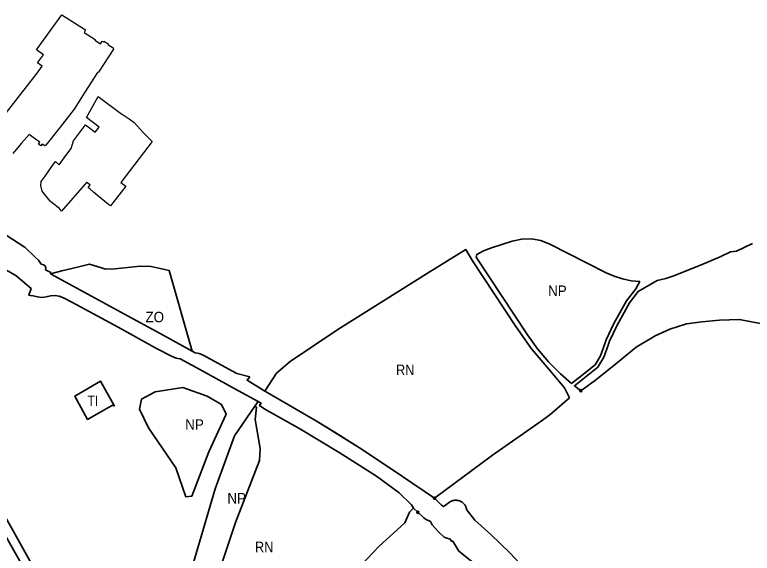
# Model space of a CAD drawing. Extents: x -650276 to -642489, y -1074311 to -1066658.
# Drawn here: x -646058 to -645218, y -1069228 to -1068615 of the extents above; entities that cross this region are included whole.
import ezdxf

# ---------------------------------------------------------------- set-up
doc = ezdxf.new("R2010")
doc.units = 0
doc.header["$LTSCALE"] = 4.8
doc.header["$PDMODE"] = 32
doc.header["$PDSIZE"] = 2.4
for name, color, linetype, lineweight in [('15', 7, 'Continuous', 35), ('24', 7, 'Continuous', 35), ('30', 7, 'Continuous', 35), ('42', 7, 'Continuous', 35), ('48', 7, 'Continuous', 35), ('61', 7, 'Continuous', 25), ('7', 7, 'Continuous', 35)]:
    doc.layers.add(name, color=color, linetype=linetype, lineweight=lineweight)
doc.layers.add('62', color=7, linetype='Continuous')

msp = doc.modelspace()

# ---------------------------------------------------------------- linework, layer by layer
at = {"layer": '15'}
msp.add_lwpolyline([(-646037.99, -1069242.88), (-646107, -1069119.41), (-646150.87, -1069037.64), (-646152.26, -1069038.76), (-646161.484, -1069046.228), (-646153.307, -1069059.947), (-646025.14, -1069285.394)], dxfattribs=at)
at = {"layer": '24'}
for points in [[(-645579.94, -1069165.52), (-645616.63, -1069140.8), (-645662.44, -1069109.89), (-645713.61, -1069078.06), (-645770.04, -1069045.34), (-645773.38, -1069043.46), (-645793.638, -1069031.021), (-645790.53, -1069027.19), (-645805.16, -1069023.52), (-645843.56, -1069002.41), (-645848.18, -1069000.48), (-645852.91, -1068999.62), (-645856.26, -1068997.79), (-645892.77, -1068977.86), (-645933.28, -1068955.74), (-645975.31, -1068932.8), (-646017.55, -1068909.75), (-646017.39, -1068908.42), (-646023.56, -1068905.05), (-646023.13, -1068903.12), (-646023.92, -1068900.73), (-646025.57, -1068899.39), (-646028.18, -1068898.89), (-646031.31, -1068894.32), (-646034.65, -1068891.12), (-646046.48, -1068879.92), (-646074.78, -1068861.51)], [(-646074.51, -1068901.9), (-646057.13, -1068911.62), (-646039.84, -1068926.67), (-646042.5, -1068933.91), (-646040.65, -1068934.59), (-646037.5, -1068934.7), (-646032.61, -1068936.1), (-646027.69, -1068936.6), (-646022.77, -1068936.12), (-646017.6, -1068934.89), (-646012.64, -1068934.34), (-646007.7, -1068935.18), (-646002.95, -1068936.95), (-645993.5, -1068942.1), (-645940.77, -1068970.74), (-645896.91, -1068994.75), (-645879.17, -1069004.02), (-645874.49, -1069005.73), (-645869.83, -1069006.45), (-645850.79, -1069016.84), (-645803.29, -1069042.92), (-645781.12, -1069055.29), (-645777.73, -1069057.2), (-645779.49, -1069059.92), (-645773.29, -1069063.99), (-645732.65, -1069086.82), (-645688.87, -1069113.44), (-645646.08, -1069140.37), (-645620.2, -1069159.26), (-645606.11, -1069172.98), (-645603.91, -1069176.86), (-645599, -1069181.48)], [(-645571.9, -1069173.43), (-645579.94, -1069165.52), (-645579.94, -1069165.52)], [(-645543.43, -1069178.39), (-645543.547, -1069177.727), (-645543.706, -1069177.053), (-645543.907, -1069176.37), (-645544.154, -1069175.682), (-645544.448, -1069174.993), (-645544.792, -1069174.308), (-645545.186, -1069173.63), (-645545.631, -1069172.966), (-645546.127, -1069172.32), (-645546.674, -1069171.699), (-645547.269, -1069171.107), (-645547.91, -1069170.551), (-645548.594, -1069170.034), (-645549.317, -1069169.563), (-645550.076, -1069169.141), (-645550.863, -1069168.772), (-645551.674, -1069168.459), (-645552.504, -1069168.203), (-645553.344, -1069168.007), (-645554.191, -1069167.87), (-645555.036, -1069167.793), (-645555.875, -1069167.772), (-645556.702, -1069167.808), (-645557.511, -1069167.896), (-645558.298, -1069168.035), (-645559.06, -1069168.219), (-645559.793, -1069168.445), (-645560.494, -1069168.709), (-645561.162, -1069169.007), (-645561.794, -1069169.334), (-645562.39, -1069169.686), (-645562.95, -1069170.06), (-645567.5, -1069173.46), (-645569.81, -1069175.03), (-645571.9, -1069173.43)], [(-645599, -1069181.48), (-645599, -1069181.48), (-645592.24, -1069187.73), (-645590.41, -1069189.45), (-645584.73, -1069191.88), (-645582.63, -1069195.88), (-645575.58, -1069203.57), (-645568.9, -1069209.87), (-645567.07, -1069210.45), (-645562.17, -1069212.02), (-645560.72, -1069214.25), (-645559.33, -1069214.54), (-645552.2, -1069225.59), (-645537.44, -1069237.41)], [(-645202.56, -1069568.23), (-645230.1, -1069525.98), (-645253.4, -1069493.06), (-645278.31, -1069461.33), (-645281.4, -1069458.4), (-645290.5, -1069449.03), (-645299.61, -1069437.97), (-645306.16, -1069425.55), (-645314.14, -1069412.54), (-645321.1, -1069405.21), (-645326.59, -1069396.64), (-645350.63, -1069363.98), (-645371.12, -1069339.47), (-645376.38, -1069332.65), (-645400.07, -1069313.32), (-645424.8, -1069295.24), (-645458.45, -1069265.56), (-645494.13, -1069227.63), (-645515.89, -1069206.66), (-645534.25, -1069190.56), (-645543.43, -1069178.39)]]:
    msp.add_lwpolyline(points, dxfattribs=at)
for p in [(-645579.94, -1069165.52), (-645599, -1069181.48)]:
    msp.add_point(p, dxfattribs=at)
at = {"layer": '30'}
msp.add_lwpolyline([(-645944.69, -1069060.7), (-645960.67, -1069032.26), (-645990.13, -1069049.3), (-645975.48, -1069075.71), (-645952.21, -1069062.4), (-645946.84, -1069059.58)], close=True, dxfattribs=at)
for points in [[(-645944.69, -1069060.7), (-645960.67, -1069032.26), (-645990.13, -1069049.3), (-645975.48, -1069075.71), (-645952.21, -1069062.4)], [(-645952.21, -1069062.4), (-645946.84, -1069059.58), (-645944.69, -1069060.7)]]:
    msp.add_lwpolyline(points, dxfattribs=at)
at = {"layer": '42'}
for points in [[(-646017.55, -1068909.75), (-646010.48, -1068907.86), (-646004.88, -1068906.5), (-645994.9, -1068904.1), (-645980.93, -1068900.85), (-645973.36, -1068898.93)], [(-645973.36, -1068898.93), (-645954.59, -1068904.41), (-645944.23, -1068904.13), (-645930.1, -1068902.47), (-645915.61, -1068901.02), (-645902.91, -1068901.43), (-645882.63, -1068905.88), (-645856.26, -1068997.79)], [(-645856.26, -1068997.79), (-645892.77, -1068977.86), (-645933.28, -1068955.74), (-645975.31, -1068932.8), (-646017.55, -1068909.75)]]:
    msp.add_lwpolyline(points, dxfattribs=at)
at = {"layer": '48'}
for points in [[(-645423.753, -1069034.862), (-645411.68, -1069025.2), (-645397.01, -1069013.46), (-645390.75, -1069003.09), (-645386.05, -1068989.63), (-645384.4, -1068984.91), (-645375.53, -1068966.56), (-645361.36, -1068940.57), (-645350.78, -1068926.76), (-645346.11, -1068918.62), (-645356.04, -1068917.65), (-645365.8, -1068915.63), (-645375.3, -1068912.58), (-645384.33, -1068908.58), (-645448.43, -1068875.95), (-645458.84, -1068871.88), (-645469.68, -1068869.93), (-645480.68, -1068870.12), (-645491.61, -1068872.47), (-645515.12, -1068880), (-645524.13, -1068883.52), (-645531.66, -1068887.61), (-645532.39, -1068890.9), (-645473.98, -1068979.47)], [(-645217.45, -1068875.09), (-645235.76, -1068883.92), (-645242.64, -1068884.8), (-645254.58, -1068890.34), (-645276.91, -1068899.79), (-645297.15, -1068907.94), (-645307.16, -1068911.97), (-645316.51, -1068915.17), (-645326.23, -1068917.37)], [(-645326.23, -1068917.37), (-645348.066, -1068929.794), (-645357.996, -1068942.757), (-645371.971, -1068968.389), (-645380.699, -1068986.445), (-645382.274, -1068990.949)], [(-645413.29, -1069042.92), (-645396.53, -1069030.88), (-645371.56, -1069010.81), (-645350.17, -1068993.33), (-645328.55, -1068980.37), (-645311.99, -1068972.74), (-645292.77, -1068966.91), (-645275.45, -1068964.38), (-645255.21, -1068962.49), (-645232.4, -1068961.67), (-645218.85, -1068964.3), (-645189.84, -1068969.91), (-645159.37, -1068981.11), (-645131.73, -1068995.69), (-645122.25, -1068993.21), (-645090.35, -1069010.56), (-645059.3, -1069027.45), (-645029.47, -1069037.71), (-644988.11, -1069042.51)], [(-645473.98, -1068979.47), (-645462.64, -1068995.27), (-645450.17, -1069010.02), (-645436.6, -1069023.76), (-645423.753, -1069034.862)], [(-645382.274, -1068990.949), (-645387.111, -1069004.801), (-645393.954, -1069016.138), (-645409.181, -1069028.323), (-645420.586, -1069037.45), (-645413.29, -1069042.92)]]:
    msp.add_lwpolyline(points, dxfattribs=at)
for points in [[(-645916.2, -1069063.8), (-645905.94, -1069085.11), (-645874.98, -1069131.01), (-645863.38, -1069163.79), (-645856.76, -1069163.17), (-645837.21, -1069112.54), (-645817.59, -1069069.6), (-645822.85, -1069058.8), (-645838.99, -1069049.31), (-645866.69, -1069039.37), (-645898.57, -1069044.24), (-645913.8, -1069052.51)], [(-645877.15, -1069319.06), (-645877.15, -1069319.06), (-645889.29, -1069330.52), (-645921.56, -1069346.6), (-645935.33, -1069340.64), (-645938.89, -1069341.56), (-645938.399, -1069347.452), (-645933.792, -1069352.53), (-645913.23, -1069356.892), (-645893.291, -1069341.938), (-645867.026, -1069327.317), (-645840.644, -1069294.052), (-645806.806, -1069193.112), (-645779.685, -1069122.296), (-645778.75, -1069108.98), (-645784.52, -1069075.66), (-645783.02, -1069061.84), (-645784.69, -1069060.74), (-645807.89, -1069094.51), (-645829.96, -1069154.65), (-645859.43, -1069254.08), (-645864.96, -1069269.78), (-645867.42, -1069274.21), (-645866.45, -1069276.32)]]:
    msp.add_lwpolyline(points, close=True, dxfattribs=at)
msp.add_point((-645413.29, -1069042.92), dxfattribs=at)
at = {"layer": '61'}
msp.add_lwpolyline([(-646070.57, -1068729.39), (-646054.6, -1068708.79), (-646033.02, -1068680.97), (-646027.29, -1068673.19), (-646032.35, -1068669.34), (-646028.98, -1068664.82), (-646025.68, -1068660.38), (-646033.67, -1068654.56), (-646004.63, -1068614.59), (-645977.65, -1068631.85), (-645979.52, -1068634.8), (-645966.82, -1068642.9), (-645967.14, -1068643.41), (-645960.63, -1068647.57), (-645958.67, -1068644.5), (-645957.36, -1068645.33), (-645956.91, -1068644.61), (-645951.87, -1068647.86), (-645952.28, -1068648.55), (-645946.37, -1068652.24), (-645945.75, -1068653.7), (-645963.17, -1068679.86), (-645964.19, -1068680.5), (-645978.4, -1068702.69), (-645990.79, -1068722.02), (-646006.77, -1068742.76), (-646023.16, -1068763.37), (-646024.22, -1068764.13), (-646027.21, -1068761.88), (-646028.77, -1068763.95), (-646031.47, -1068761.91), (-646029.91, -1068759.84), (-646033.21, -1068757.35), (-646041.889, -1068750.882), (-646050.57, -1068760.83), (-646060.78, -1068772.53)], dxfattribs=at)
msp.add_lwpolyline([(-645966.626, -1068748.419), (-645962.14, -1068742.51), (-645976.82, -1068731.5), (-645963.52, -1068707.92), (-645936.46, -1068727.71), (-645934.95, -1068728.69), (-645927.9, -1068733.25), (-645922.38, -1068737.4), (-645911.64, -1068749.19), (-645901.71, -1068759.09), (-645937.37, -1068805.77), (-645931.74, -1068810.06), (-645949.45, -1068832.34), (-645951.53, -1068830.71), (-645955.59, -1068827.42), (-645959.81, -1068823.96), (-645964.09, -1068820.54), (-645968.55, -1068816.88), (-645972.63, -1068813.49), (-645974.79, -1068811.55), (-645972.63, -1068808.55), (-645976.52, -1068805.7), (-645979.15, -1068808.68), (-646005.18, -1068838.43), (-646007.27, -1068835.51), (-646009.97, -1068833.45), (-646012.63, -1068831.33), (-646015.29, -1068829.21), (-646017.95, -1068827.09), (-646027.13, -1068815.63), (-646028.59, -1068809.26), (-646028.24, -1068804.53), (-646023.94, -1068798.68), (-646016.36, -1068787.54), (-646012.15, -1068781.94), (-646007.68, -1068785.56), (-646000.11, -1068774.8), (-645994.29, -1068767.03), (-645991.63, -1068758.23), (-645977.81, -1068739.99)], close=True, dxfattribs=at)
at = {"layer": '7'}
msp.add_lwpolyline([(-645770.04, -1069045.34), (-645713.61, -1069078.06), (-645694.447, -1069089.98), (-645662.44, -1069109.89), (-645616.63, -1069140.8), (-645579.94, -1069165.52), (-645514.08, -1069116.5), (-645459.5, -1069078.59), (-645448.49, -1069070.45), (-645426.3, -1069051.02), (-645431.85, -1069039.83), (-645449.72, -1069018.58), (-645469.5, -1068995.09), (-645487.38, -1068969.87), (-645536.63, -1068894.79), (-645544.33, -1068882.17), (-645586.28, -1068907.71), (-645690.34, -1068973.16), (-645744.65, -1069009.71), (-645760.07, -1069023.11), (-645773.38, -1069043.46)], close=True, dxfattribs=at)
msp.add_lwpolyline([(-645675.82, -1069254.48), (-645643.34, -1069220.59), (-645613.9, -1069193.45), (-645608.71, -1069181.51), (-645603.91, -1069176.86), (-645606.11, -1069172.98), (-645620.2, -1069159.26), (-645646.08, -1069140.37), (-645688.87, -1069113.44), (-645732.65, -1069086.82), (-645773.29, -1069063.99), (-645779.49, -1069059.92), (-645777.73, -1069057.2), (-645781.12, -1069055.29), (-645784.69, -1069060.74), (-645783.02, -1069061.84), (-645784.52, -1069075.66), (-645778.75, -1069108.98), (-645779.685, -1069122.296), (-645806.806, -1069193.112), (-645840.644, -1069294.052)], dxfattribs=at)

# ---------------------------------------------------------------- texts
at = {"layer": '62'}
for s, width, p in [('NP', 0.95, (-645450.583, -1068935.041)), ('ZO', 0.95, (-645909.476, -1068965.017)), ('RN', 0.9, (-645623.83, -1069025.21)), ('TI', 0.85, (-645975.476, -1069060.535)), ('NP', 0.95, (-645864.111, -1069087.517)), ('NP', 0.95, (-645816.111, -1069171.517)), ('RN', 0.9, (-645784.603, -1069226.978))]:
    msp.add_text(s, height=12, dxfattribs=dict(at, width=width)).set_placement(p)

doc.saveas('drawing.dxf')
